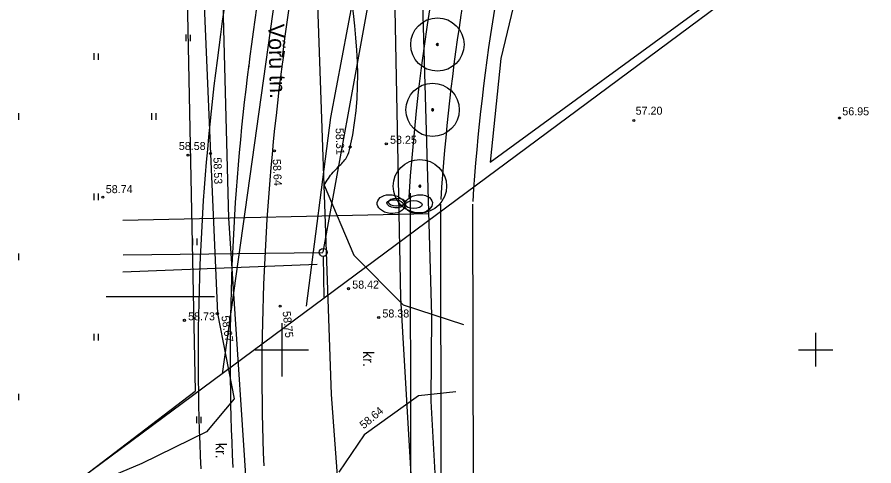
# Model space of a CAD drawing. Extents: x 9156 to 9809, y 2728 to 4000.
# Drawn here: x 9375.2 to 9455.5, y 3389.1 to 3431.2 of the extents above; entities that cross this region are included whole.
import ezdxf

# ---------------------------------------------------------------- set-up
doc = ezdxf.new("R2010")
doc.units = 0
for name, color, linetype in [('Level 1', 7, 'Continuous'), ('Level 12', 7, 'Continuous'), ('Level 14', 7, 'Continuous'), ('Level 15', 7, 'Continuous'), ('Level 16', 7, 'Continuous'), ('Level 17', 7, 'Continuous'), ('Level 18', 7, 'Continuous'), ('Level 54', 7, 'Continuous'), ('Level 56', 7, 'Continuous'), ('Level 58', 7, 'Continuous'), ('Level 7', 7, 'Continuous'), ('Level 8', 7, 'Continuous'), ('Level 9', 7, 'Continuous')]:
    doc.layers.add(name, color=color, linetype=linetype)

# ---------------------------------------------------------------- blocks, each defined once
blk = doc.blocks.new('KKOL')
at = {"layer": 'Level 58'}
for p, q in [((0, 1.59349), (0, -1.5935)), ((-1.5935, 0), (1.59349, 0))]:
    blk.add_line(p, q, dxfattribs=at)

msp = doc.modelspace()

# ---------------------------------------------------------------- linework, layer by layer
at = {"layer": 'Level 1'}
msp.add_line((9524.24, 3494.13), (9347.38, 3362.85), dxfattribs=at)
msp.add_line((9524.24, 3494.13), (9347.38, 3362.85), dxfattribs=at)
at = {"layer": 'Level 12'}
for p, q in [((9401.981, 3451.869), (9394.391, 3397.745)), ((9393.691, 3404.947), (9383.536, 3404.947))]:
    msp.add_line(p, q, dxfattribs=at)
at = {"layer": 'Level 14'}
for p, q in [((9403.878, 3409.152), (9413.752, 3463.774)), ((9403.824, 3409.093), (9385.129, 3408.862)), ((9403.964, 3404.851), (9403.886, 3408.743))]:
    msp.add_line(p, q, dxfattribs=at)
msp.add_circle((9403.87, 3409.117), 0.375, dxfattribs=at)
at = {"layer": 'Level 15'}
msp.add_line((9413.789, 3412.738), (9385.112, 3412.102), dxfattribs=at)
at = {"layer": 'Level 16'}
for p, q in [((9404.585, 3421.76), (9410.928, 3455.57)), ((9402.32, 3404.084), (9404.585, 3421.76)), ((9403.311, 3407.988), (9385.104, 3407.256))]:
    msp.add_line(p, q, dxfattribs=at)
at = {"layer": 'Level 17'}
for p, q in [((9414.868, 3413.629), (9414.977, 3329.636)), ((9417.868, 3413.633), (9417.977, 3329.636))]:
    msp.add_line(p, q, dxfattribs=at)
for centre, radius, start, end in [((9607.784, 3401.679), 215.35, 152.14387, 173.22057), ((9607.784, 3401.679), 212.35, 153.57103, 173.32026), ((9607.784, 3401.679), 190.3, 153.02623, 176.31932), ((9607.784, 3401.679), 193.3, 154.37515, 176.31932), ((9617.5, 3397.887), 219.375, 172.11283, 182.2946), ((9608.149, 3399.437), 216, 172.63735, 182.81912), ((9608.149, 3399.437), 213, 172.63735, 182.81912)]:
    msp.add_arc(centre, radius, start, end, dxfattribs=at)
at = {"layer": 'Level 18'}
msp.add_line((9412.019, 3414.669), (9412.139, 3329.632), dxfattribs=at)
for radius, start, end in [(209.35, 155.52551, 172.93494), (196.3, 157.34047, 176.31932)]:
    msp.add_arc((9607.784, 3401.679), radius, start, end, dxfattribs=at)
at = {"layer": 'Level 54'}
for p, q in [((9392.539, 3436.843), (9393.311, 3418.368)), ((9391.012, 3429.539), (9391.012, 3428.919)), ((9391.418, 3429.528), (9391.418, 3428.919)), ((9382.392, 3427.795), (9382.392, 3427.175)), ((9382.798, 3427.784), (9382.798, 3427.175)), ((9375.322, 3422.164), (9375.322, 3421.555)), ((9387.798, 3422.175), (9387.798, 3421.555)), ((9388.204, 3422.164), (9388.204, 3421.555)), ((9406.398, 3419.011), (9406.398, 3419.011)), ((9409.782, 3419.306), (9409.782, 3419.306)), ((9391.211, 3418.235), (9391.211, 3418.235)), ((9393.311, 3418.368), (9393.956, 3403.383)), ((9393.316, 3418.393), (9393.316, 3418.393)), ((9399.295, 3418.642), (9399.295, 3418.642)), ((9403.972, 3415.413), (9403.972, 3415.413)), ((9382.392, 3414.644), (9382.392, 3414.024)), ((9382.798, 3414.632), (9382.798, 3414.024)), ((9395.019, 3412.343), (9395.019, 3412.343)), ((9391.612, 3410.432), (9391.612, 3409.812)), ((9392.017, 3410.421), (9392.017, 3409.812)), ((9375.322, 3409.012), (9375.322, 3408.403)), ((9406.746, 3408.861), (9406.746, 3408.861)), ((9406.24, 3405.726), (9406.24, 3405.726)), ((9399.834, 3404.078), (9399.834, 3404.078)), ((9411.362, 3404.207), (9411.362, 3404.207)), ((9390.868, 3402.754), (9390.868, 3402.754)), ((9393.956, 3403.383), (9393.956, 3403.383)), ((9393.956, 3403.383), (9395.518, 3395.381)), ((9409.067, 3403.018), (9409.067, 3403.018)), ((9414.011, 3403.198), (9414.011, 3403.198)), ((9400, 3402.5), (9400, 3397.5)), ((9400, 3402.5), (9400, 3397.5)), ((9400, 3402.5), (9400, 3397.5)), ((9382.392, 3401.492), (9382.392, 3400.872)), ((9382.798, 3401.481), (9382.798, 3400.872)), ((9450, 3401.25), (9450, 3398.75)), ((9397.5, 3400), (9402.5, 3400)), ((9397.5, 3400), (9402.5, 3400)), ((9397.5, 3400), (9402.5, 3400)), ((9448.75, 3400), (9451.25, 3400)), ((9375.322, 3395.861), (9375.322, 3395.252)), ((9404.623, 3395.803), (9404.623, 3395.803)), ((9412.811, 3395.687), (9412.811, 3395.687)), ((9395.518, 3395.381), (9395.518, 3395.381)), ((9413.966, 3395.158), (9413.966, 3395.158)), ((9392.012, 3393.725), (9392.012, 3393.105)), ((9392.417, 3393.714), (9392.417, 3393.105)), ((9392.942, 3392.307), (9392.942, 3392.307)), ((9407.7, 3392.021), (9407.7, 3392.021)), ((9386.883, 3389.337), (9370.486, 3382.436))]:
    msp.add_line(p, q, dxfattribs=at)
for points in [[(9397.129, 3380.652), (9395.019, 3412.343), (9393.756, 3460.883), (9392.807, 3509.978), (9391.971, 3559.264), (9391.116, 3614.638), (9387.944, 3630.289), (9387.153, 3640.427)], [(9406.951, 3592.745), (9404.9, 3589.399), (9400.65, 3580.127), (9400.669, 3573.249), (9401.91, 3506.844), (9403.071, 3439.533), (9404.623, 3395.803), (9405.779, 3380.148)], [(9410.662, 3513.259), (9411.129, 3502.78), (9414.011, 3403.198), (9413.966, 3395.158), (9414.527, 3385.035)], [(9412.616, 3379.749), (9411.152, 3404.875), (9409.689, 3479.597), (9409.112, 3500.044)], [(9403.972, 3415.413), (9406.746, 3408.861), (9411.362, 3404.207), (9416.996, 3402.372)], [(9416.306, 3396.041), (9412.811, 3395.687), (9407.7, 3392.021), (9405.327, 3388.529)], [(9395.518, 3395.381), (9392.942, 3392.307), (9386.883, 3389.337)]]:
    msp.add_lwpolyline(points, dxfattribs=at)
for centre, radius in [((9432.968, 3421.494), 0.0909), ((9452.236, 3421.721), 0.0909), ((9406.398, 3419.011), 0.1), ((9409.782, 3419.306), 0.1), ((9391.211, 3418.235), 0.1), ((9393.316, 3418.393), 0.1), ((9399.295, 3418.642), 0.1), ((9383.226, 3414.311), 0.0909), ((9406.24, 3405.726), 0.1), ((9399.834, 3404.078), 0.1), ((9390.868, 3402.754), 0.1), ((9393.956, 3403.383), 0.1), ((9409.067, 3403.018), 0.1)]:
    msp.add_circle(centre, radius, dxfattribs=at)
msp.add_spline([(9403.972, 3415.413), (9404.351, 3416.063), (9405.307, 3417.16), (9406.059, 3418.023), (9406.398, 3419.011), (9405.885, 3437.211)], degree=3, dxfattribs=at)
at = {"layer": 'Level 56'}
for p, q in [((9412.019, 3414.669), (9412.139, 3329.632)), ((9414.868, 3413.629), (9414.977, 3329.636)), ((9417.868, 3413.633), (9417.977, 3329.636))]:
    msp.add_line(p, q, dxfattribs=at)
for centre, radius, start, end in [((9607.784, 3401.679), 215.35, 152.14387, 173.22057), ((9607.784, 3401.679), 212.35, 153.57103, 173.32026), ((9607.784, 3401.679), 209.35, 155.52551, 172.93494), ((9607.784, 3401.679), 190.3, 153.02623, 176.31932), ((9607.784, 3401.679), 193.3, 154.37515, 176.31932), ((9607.784, 3401.679), 196.3, 157.34047, 176.31932), ((9617.5, 3397.887), 219.375, 172.11283, 182.2946), ((9608.149, 3399.437), 216, 172.63735, 182.81912), ((9608.149, 3399.437), 213, 172.63735, 182.81912)]:
    msp.add_arc(centre, radius, start, end, dxfattribs=at)
at = {"layer": 'Level 7'}
for p, q in [((9389.67, 3504.41), (9391.882, 3396.104)), ((9419.514, 3417.583), (9493.972, 3472.006)), ((9429.106, 3463.441), (9420.511, 3427.312)), ((9420.511, 3427.312), (9419.514, 3417.583)), ((9347.788, 3362.52), (9391.882, 3396.104))]:
    msp.add_line(p, q, dxfattribs=at)
at = {"layer": 'Level 8'}
for centre, major_axis, ratio in [((9410.218, 3413.648), (1.285, -0.15), 0.674652), ((9410.218, 3413.648), (1.285, -0.15), 0.674652), ((9410.218, 3413.648), (1.285, -0.15), 0.674652), ((9410.218, 3413.648), (1.285, -0.15), 0.674652), ((9410.613, 3413.685), (0.774, -0.072), 0.486914), ((9410.613, 3413.685), (0.774, -0.072), 0.486914), ((9410.613, 3413.685), (0.774, -0.072), 0.486914), ((9410.613, 3413.685), (0.774, -0.072), 0.486914), ((9410.765, 3413.831), (-0.778, 0.002), 0.486914), ((9410.765, 3413.831), (-0.778, 0.002), 0.486914), ((9410.765, 3413.831), (-0.778, 0.002), 0.486914), ((9410.765, 3413.831), (-0.778, 0.002), 0.486914), ((9412.81, 3413.648), (-1.285, -0.15), 0.674652), ((9412.81, 3413.648), (-1.285, -0.15), 0.674652), ((9412.81, 3413.648), (-1.285, -0.15), 0.674652), ((9412.81, 3413.648), (-1.285, -0.15), 0.674652), ((9412.351, 3413.604), (-0.778, 0.002), 0.486914), ((9412.351, 3413.604), (-0.778, 0.002), 0.486914), ((9412.351, 3413.604), (-0.778, 0.002), 0.486914), ((9412.351, 3413.604), (-0.778, 0.002), 0.486914)]:
    msp.add_ellipse(centre, major_axis=major_axis, ratio=ratio, dxfattribs=at)
at = {"layer": 'Level 9'}
for p, q in [((9414.486, 3428.625), (9414.465, 3428.628)), ((9414.465, 3428.599), (9414.486, 3428.603)), ((9414.473, 3428.655), (9414.493, 3428.647)), ((9414.493, 3428.581), (9414.473, 3428.571)), ((9414.488, 3428.548), (9414.505, 3428.562)), ((9414.505, 3428.665), (9414.489, 3428.679)), ((9414.51, 3428.698), (9414.521, 3428.679)), ((9414.522, 3428.547), (9414.51, 3428.529)), ((9414.543, 3428.689), (9414.536, 3428.71)), ((9414.536, 3428.517), (9414.542, 3428.538)), ((9414.575, 3428.612), (9414.554, 3428.612)), ((9414.564, 3428.714), (9414.564, 3428.692)), ((9414.564, 3428.534), (9414.564, 3428.513)), ((9414.565, 3428.602), (9414.565, 3428.623)), ((9414.586, 3428.689), (9414.592, 3428.71)), ((9414.592, 3428.516), (9414.587, 3428.538)), ((9414.607, 3428.546), (9414.619, 3428.528)), ((9414.618, 3428.698), (9414.608, 3428.679)), ((9414.624, 3428.665), (9414.64, 3428.679)), ((9414.641, 3428.548), (9414.625, 3428.563)), ((9414.656, 3428.655), (9414.636, 3428.645)), ((9414.637, 3428.581), (9414.656, 3428.572)), ((9414.643, 3428.624), (9414.664, 3428.628)), ((9414.664, 3428.6), (9414.643, 3428.603)), ((9414.039, 3422.504), (9414.017, 3422.507)), ((9414.017, 3422.478), (9414.039, 3422.482)), ((9414.026, 3422.534), (9414.046, 3422.526)), ((9414.045, 3422.46), (9414.026, 3422.45)), ((9414.058, 3422.544), (9414.041, 3422.558)), ((9414.041, 3422.427), (9414.057, 3422.441)), ((9414.062, 3422.577), (9414.074, 3422.558)), ((9414.075, 3422.426), (9414.062, 3422.408)), ((9414.088, 3422.396), (9414.094, 3422.417)), ((9414.095, 3422.568), (9414.089, 3422.589)), ((9414.128, 3422.491), (9414.107, 3422.491)), ((9414.117, 3422.413), (9414.116, 3422.392)), ((9414.117, 3422.593), (9414.117, 3422.571)), ((9414.117, 3422.481), (9414.117, 3422.502)), ((9414.138, 3422.568), (9414.144, 3422.589)), ((9414.145, 3422.396), (9414.139, 3422.417)), ((9414.159, 3422.426), (9414.171, 3422.407)), ((9414.171, 3422.577), (9414.16, 3422.558)), ((9414.176, 3422.544), (9414.193, 3422.558)), ((9414.194, 3422.427), (9414.177, 3422.442)), ((9414.208, 3422.534), (9414.189, 3422.524)), ((9414.189, 3422.46), (9414.209, 3422.451)), ((9414.195, 3422.503), (9414.216, 3422.507)), ((9414.217, 3422.479), (9414.195, 3422.482)), ((9412.846, 3415.338), (9412.824, 3415.341)), ((9412.824, 3415.312), (9412.845, 3415.316)), ((9412.832, 3415.368), (9412.852, 3415.36)), ((9412.852, 3415.294), (9412.832, 3415.284)), ((9412.847, 3415.261), (9412.864, 3415.275)), ((9412.864, 3415.378), (9412.848, 3415.392)), ((9412.869, 3415.411), (9412.881, 3415.392)), ((9412.881, 3415.26), (9412.869, 3415.242)), ((9412.902, 3415.402), (9412.895, 3415.423)), ((9412.895, 3415.23), (9412.901, 3415.251)), ((9412.934, 3415.325), (9412.913, 3415.325)), ((9412.923, 3415.427), (9412.923, 3415.405)), ((9412.923, 3415.248), (9412.923, 3415.226)), ((9412.924, 3415.315), (9412.924, 3415.336)), ((9412.945, 3415.402), (9412.951, 3415.423)), ((9412.951, 3415.23), (9412.946, 3415.251)), ((9412.966, 3415.26), (9412.978, 3415.242)), ((9412.977, 3415.411), (9412.967, 3415.392)), ((9412.983, 3415.378), (9413, 3415.392)), ((9413, 3415.261), (9412.984, 3415.276)), ((9413.015, 3415.368), (9412.996, 3415.358)), ((9412.996, 3415.294), (9413.016, 3415.286)), ((9413.002, 3415.337), (9413.023, 3415.341)), ((9413.023, 3415.313), (9413.002, 3415.316))]:
    msp.add_line(p, q, dxfattribs=at)
for centre in [(9414.565, 3428.612), (9414.117, 3422.491), (9412.924, 3415.325)]:
    msp.add_circle(centre, 2.5, dxfattribs=at)
for centre, radius, start, end in [((9414.565, 3428.613), 0.101, 155.31226, 171.70421), ((9414.565, 3428.613), 0.101, 187.96706, 204.86254), ((9414.565, 3428.613), 0.0788, 171.54306, 187.6203), ((9414.565, 3428.613), 0.101, 220.71222, 237.11658), ((9414.565, 3428.613), 0.101, 122.84338, 139.02216), ((9414.565, 3428.613), 0.0788, 138.64322, 154.57953), ((9414.565, 3428.613), 0.0788, 204.45291, 220.47744), ((9414.565, 3428.613), 0.0788, 105.95586, 123.05638), ((9414.565, 3428.613), 0.0788, 237.451, 253.08433), ((9414.565, 3428.613), 0.101, 90.03559, 106.34199), ((9414.565, 3428.613), 0.101, 253.29517, 269.57177), ((9414.565, 3428.613), 0.0788, 74.31, 90.04303), ((9414.565, 3428.613), 0.0788, 269.94612, 286.34731), ((9414.565, 3428.613), 0.101, 57.61079, 74.19806), ((9414.565, 3428.613), 0.101, 285.97198, 302.5562), ((9414.565, 3428.613), 0.0788, 302.25403, 320.08604), ((9414.565, 3428.613), 0.0788, 41.20616, 56.77954), ((9414.565, 3428.613), 0.0788, 8.06191, 24.03317), ((9414.565, 3428.613), 0.0788, 336.05568, 352.75584), ((9414.565, 3428.613), 0.101, 24.53942, 40.98516), ((9414.565, 3428.613), 0.101, 319.77774, 336.07384), ((9414.565, 3428.613), 0.101, 352.27003, 8.58296), ((9414.117, 3422.492), 0.101, 155.31226, 171.70421), ((9414.117, 3422.492), 0.101, 187.96706, 204.86254), ((9414.117, 3422.492), 0.0788, 171.54306, 187.6203), ((9414.117, 3422.492), 0.101, 122.84338, 139.02216), ((9414.117, 3422.492), 0.101, 220.71222, 237.11658), ((9414.117, 3422.492), 0.0788, 204.45291, 220.47744), ((9414.117, 3422.492), 0.0788, 138.64322, 154.57953), ((9414.117, 3422.492), 0.0788, 105.95586, 123.05638), ((9414.117, 3422.492), 0.0788, 237.451, 253.08433), ((9414.117, 3422.492), 0.101, 253.29517, 269.57177), ((9414.117, 3422.492), 0.101, 90.03559, 106.34199), ((9414.117, 3422.492), 0.0788, 74.31, 90.04303), ((9414.117, 3422.492), 0.0788, 269.94612, 286.34731), ((9414.117, 3422.492), 0.101, 57.61079, 74.19806), ((9414.117, 3422.492), 0.101, 285.97198, 302.5562), ((9414.117, 3422.492), 0.0788, 302.25403, 320.08604), ((9414.117, 3422.492), 0.0788, 41.20616, 56.77954), ((9414.117, 3422.492), 0.0788, 8.06191, 24.03317), ((9414.117, 3422.492), 0.0788, 336.05568, 352.75584), ((9414.117, 3422.492), 0.101, 24.53942, 40.98516), ((9414.117, 3422.492), 0.101, 319.77774, 336.07384), ((9414.117, 3422.492), 0.101, 352.27003, 8.58296), ((9412.924, 3415.326), 0.101, 155.31226, 171.70421), ((9412.924, 3415.326), 0.101, 187.96706, 204.86254), ((9412.924, 3415.326), 0.0788, 171.54306, 187.6203), ((9412.924, 3415.326), 0.101, 220.71222, 237.11658), ((9412.924, 3415.326), 0.101, 122.84338, 139.02216), ((9412.924, 3415.326), 0.0788, 138.64322, 154.57953), ((9412.924, 3415.326), 0.0788, 204.45291, 220.47744), ((9412.924, 3415.326), 0.0788, 105.95586, 123.05638), ((9412.924, 3415.326), 0.0788, 237.451, 253.08433), ((9412.924, 3415.326), 0.101, 90.03559, 106.34199), ((9412.924, 3415.326), 0.101, 253.29517, 269.57177), ((9412.924, 3415.326), 0.0788, 269.94612, 286.34731), ((9412.924, 3415.326), 0.0788, 74.31, 90.04303), ((9412.924, 3415.326), 0.101, 57.61079, 74.19806), ((9412.924, 3415.326), 0.101, 285.97198, 302.5562), ((9412.924, 3415.326), 0.0788, 302.25403, 320.08604), ((9412.924, 3415.326), 0.0788, 41.20616, 56.77954), ((9412.924, 3415.326), 0.0788, 8.06191, 24.03317), ((9412.924, 3415.326), 0.0788, 336.05568, 352.75584), ((9412.924, 3415.326), 0.101, 24.53942, 40.98516), ((9412.924, 3415.326), 0.101, 319.77774, 336.07384), ((9412.924, 3415.326), 0.101, 352.27003, 8.58296)]:
    msp.add_arc(centre, radius, start, end, dxfattribs=at)

# ---------------------------------------------------------------- block references
at = {"layer": 'Level 54'}
msp.add_blockref('KKOL', (9450, 3400), dxfattribs=at)

# ---------------------------------------------------------------- texts
for s, height, rotation, p in [('Võru tn.', 1.5, 271.29152, (9398.73, 3430.532)), ('58.31', 0.75, 271.64391, (9405.03, 3420.782)), ('58.53', 0.75, 271.97246, (9393.585, 3418.011)), ('58.64', 0.75, 272.66039, (9399.14, 3417.853)), ('58.75', 0.75, 276.13153, (9400.064, 3403.574)), ('58.67', 0.75, 279.14893, (9394.323, 3403.139)), ('kr.', 1, 270.20803, (9407.603, 3399.867)), ('58.64', 0.75, 40.16913, (9407.667, 3392.526)), ('kr.', 1, 270.20803, (9393.806, 3391.26))]:
    msp.add_text(s, height=height, rotation=rotation, dxfattribs=at).set_placement(p)
for s, p in [('57.20', (9433.138, 3422.032)), ('56.95', (9452.497, 3421.976)), ('58.25', (9410.132, 3419.306)), ('58.58', (9390.347, 3418.724)), ('58.74', (9383.501, 3414.675)), ('58.42', (9406.59, 3405.726)), ('58.38', (9409.417, 3403.018)), ('58.73', (9391.218, 3402.754))]:
    msp.add_text(s, height=0.75, dxfattribs=at).set_placement(p)

doc.saveas('drawing.dxf')
